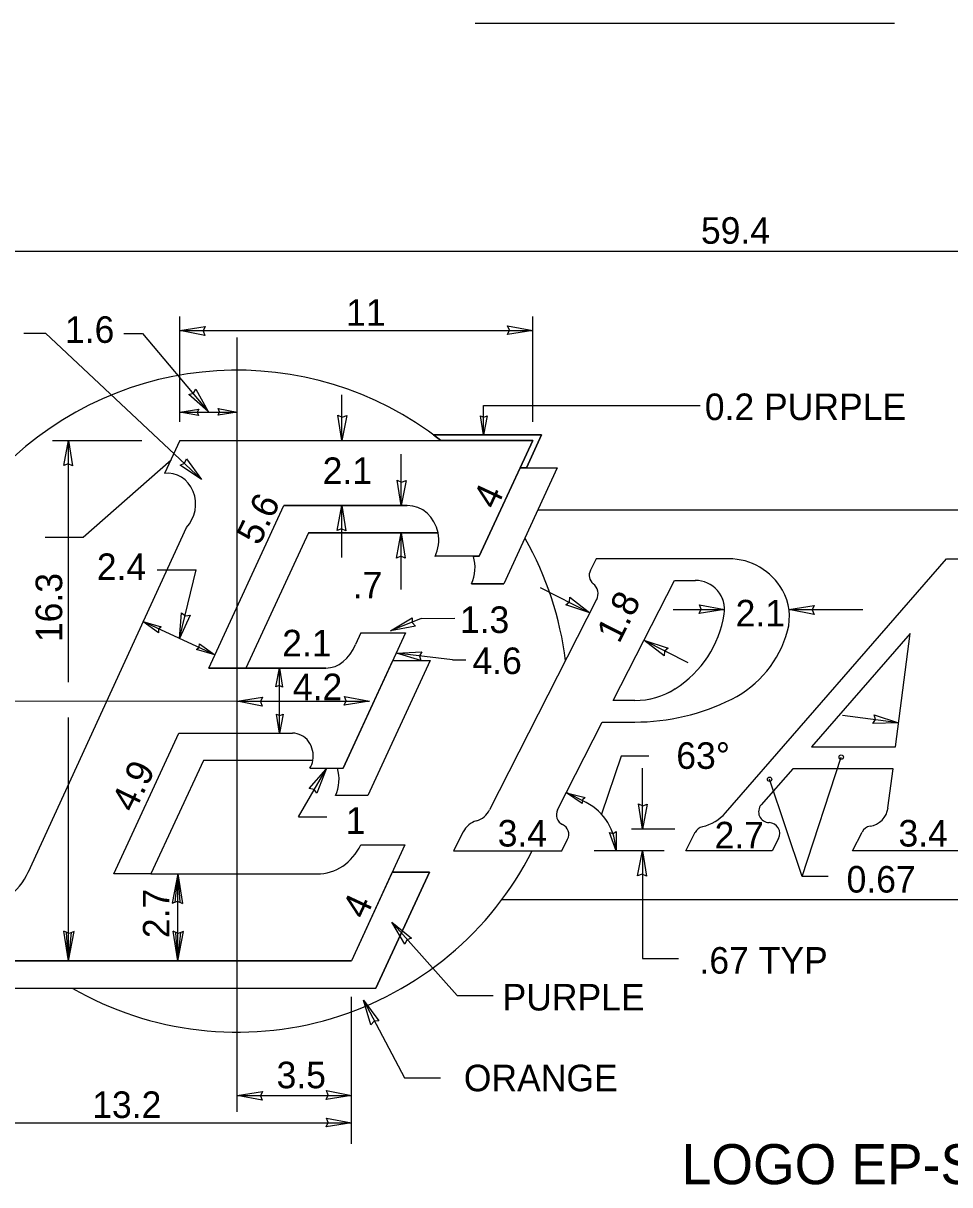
# Model space of a CAD drawing. Extents: x 10268197 to 10268826, y 2141503 to 2142677.
# Drawn here: x 10268506.08 to 10268526.03, y 2142338.69 to 2142363.7 of the extents above; entities that cross this region are included whole.
import ezdxf

# ---------------------------------------------------------------- set-up
doc = ezdxf.new("R2010")
doc.units = 0
doc.layers.add('Default', color=7, linetype='Continuous')
doc.layers.add('TextDetails', color=7, linetype='Continuous')

msp = doc.modelspace()

# ---------------------------------------------------------------- linework, layer by layer
at = {"layer": 'Default'}
for p, q in [((10268501.67, 2142358.79), (10268542.432, 2142358.79)), ((10268509.455, 2142355.114), (10268509.455, 2142357.385)), ((10268517.054, 2142355.114), (10268517.054, 2142357.385)), ((10268509.455, 2142357.079), (10268517.054, 2142357.079)), ((10268508.25, 2142357.02), (10268508.653, 2142357.02)), ((10268508.653, 2142357.02), (10268510.066, 2142355.339)), ((10268510.689, 2142349.102), (10268510.689, 2142356.928)), ((10268512.945, 2142354.713), (10268512.945, 2142355.696)), ((10268509.455, 2142355.326), (10268510.689, 2142355.326)), ((10268515.994, 2142354.837), (10268515.994, 2142355.47)), ((10268515.994, 2142355.47), (10268520.663, 2142355.47)), ((10268515.079, 2142354.713), (10268514.916, 2142354.837)), ((10268514.916, 2142354.837), (10268517.247, 2142354.837)), ((10268514.916, 2142354.837), (10268517.247, 2142354.837)), ((10268517.247, 2142354.837), (10268516.918, 2142354.124)), ((10268517.247, 2142354.837), (10268516.918, 2142354.124)), ((10268506.717, 2142354.713), (10268508.635, 2142354.713)), ((10268507.062, 2142349.514), (10268507.062, 2142354.713)), ((10268509.455, 2142354.713), (10268509.127, 2142354)), ((10268509.455, 2142354.713), (10268517.054, 2142354.713)), ((10268517.054, 2142354.713), (10268515.079, 2142354.713)), ((10268517.054, 2142354.713), (10268515.902, 2142352.22)), ((10268516.783, 2142354.124), (10268517.054, 2142354.713)), ((10268507.376, 2142352.632), (10268509.266, 2142354.295)), ((10268514.223, 2142353.314), (10268514.223, 2142354.42)), ((10268515.902, 2142352.22), (10268516.783, 2142354.124)), ((10268517.582, 2142354.124), (10268516.429, 2142351.63)), ((10268517.582, 2142354.124), (10268516.429, 2142351.63)), ((10268516.783, 2142354.124), (10268517.582, 2142354.124)), ((10268516.783, 2142354.124), (10268517.582, 2142354.124)), ((10268516.783, 2142354.124), (10268517.582, 2142354.124)), ((10268516.918, 2142354.124), (10268516.783, 2142354.124)), ((10268510.081, 2142349.813), (10268511.696, 2142353.314)), ((10268510.081, 2142349.813), (10268511.696, 2142353.314)), ((10268510.081, 2142349.813), (10268511.696, 2142353.314)), ((10268511.696, 2142353.314), (10268514.353, 2142353.314)), ((10268511.696, 2142353.314), (10268514.353, 2142353.314)), ((10268512.196, 2142353.314), (10268511.696, 2142353.314)), ((10268511.696, 2142353.314), (10268514.353, 2142353.314)), ((10268511.696, 2142353.314), (10268514.353, 2142353.314)), ((10268514.353, 2142353.314), (10268512.196, 2142353.314)), ((10268512.945, 2142352.193), (10268512.945, 2142353.314)), ((10268542.432, 2142353.216), (10268517.161, 2142353.216)), ((10268506.2, 2142345.432), (10268509.597, 2142352.844)), ((10268506.56, 2142352.632), (10268507.376, 2142352.632)), ((10268512.225, 2142352.724), (10268510.879, 2142349.813)), ((10268512.225, 2142352.724), (10268510.879, 2142349.813)), ((10268512.225, 2142352.724), (10268510.879, 2142349.813)), ((10268515.015, 2142352.724), (10268512.225, 2142352.724)), ((10268512.225, 2142352.724), (10268515.015, 2142352.724)), ((10268515.015, 2142352.724), (10268512.225, 2142352.724)), ((10268515.015, 2142352.724), (10268512.723, 2142352.724)), ((10268514.223, 2142351.509), (10268514.223, 2142352.724)), ((10268515.902, 2142352.22), (10268514.952, 2142352.22)), ((10268515.775, 2142352.22), (10268515.902, 2142352.22)), ((10268518.424, 2142352.168), (10268518.296, 2142351.919)), ((10268521.277, 2142352.168), (10268518.424, 2142352.168)), ((10268521.206, 2142346.697), (10268525.961, 2142352.168)), ((10268525.961, 2142352.168), (10268526.799, 2142352.168)), ((10268508.966, 2142351.929), (10268509.811, 2142351.929)), ((10268509.448, 2142350.452), (10268509.811, 2142351.929)), ((10268515.734, 2142351.63), (10268516.429, 2142351.63)), ((10268516.429, 2142351.63), (10268515.734, 2142351.63)), ((10268517.213, 2142351.552), (10268518.287, 2142351.004)), ((10268518.789, 2142349.118), (10268520.107, 2142351.703)), ((10268518.789, 2142349.118), (10268520.107, 2142351.702)), ((10268520.107, 2142351.703), (10268520.556, 2142351.703)), ((10268520.107, 2142351.702), (10268520.556, 2142351.702)), ((10268518.431, 2142351.288), (10268516.126, 2142346.762)), ((10268520.08, 2142351.074), (10268521.185, 2142351.074)), ((10268522.572, 2142351.074), (10268524.16, 2142351.074)), ((10268510.213, 2142350.099), (10268508.659, 2142350.815)), ((10268514.653, 2142350.882), (10268513.989, 2142350.617)), ((10268514.653, 2142350.882), (10268515.379, 2142350.886)), ((10268514.318, 2142350.57), (10268512.973, 2142347.658)), ((10268513.354, 2142350.57), (10268513.24, 2142350.322)), ((10268513.354, 2142350.57), (10268514.318, 2142350.57)), ((10268525.182, 2142350.562), (10268523.055, 2142348.116)), ((10268525.182, 2142350.561), (10268523.055, 2142348.116)), ((10268524.863, 2142348.116), (10268525.182, 2142350.562)), ((10268524.863, 2142348.116), (10268525.182, 2142350.561)), ((10268519.45, 2142350.413), (10268520.391, 2142349.934)), ((10268515.328, 2142349.989), (10268514.118, 2142350.138)), ((10268510.081, 2142349.813), (10268512.603, 2142349.813)), ((10268512.603, 2142349.813), (10268510.081, 2142349.813)), ((10268510.879, 2142349.813), (10268510.081, 2142349.813)), ((10268510.081, 2142349.813), (10268512.603, 2142349.813)), ((10268512.603, 2142349.813), (10268510.081, 2142349.813)), ((10268510.58, 2142349.813), (10268511.38, 2142349.813)), ((10268511.601, 2142348.414), (10268511.601, 2142349.813)), ((10268512.973, 2142347.658), (10268514.045, 2142349.98)), ((10268514.844, 2142349.98), (10268513.501, 2142347.07)), ((10268514.844, 2142349.98), (10268513.501, 2142347.07)), ((10268514.045, 2142349.98), (10268514.844, 2142349.98)), ((10268514.045, 2142349.98), (10268514.844, 2142349.98)), ((10268515.328, 2142349.989), (10268515.616, 2142349.99)), ((10268510.689, 2142349.102), (10268503.564, 2142349.091)), ((10268510.689, 2142340.264), (10268510.689, 2142349.102)), ((10268510.689, 2142349.102), (10268513.54, 2142349.102)), ((10268519.251, 2142349.118), (10268518.789, 2142349.118)), ((10268519.251, 2142349.118), (10268518.789, 2142349.118)), ((10268524.931, 2142348.637), (10268523.728, 2142348.793)), ((10268507.062, 2142343.516), (10268507.062, 2142348.748)), ((10268517.589, 2142346.762), (10268518.552, 2142348.652)), ((10268518.552, 2142348.652), (10268519.251, 2142348.652)), ((10268508.033, 2142345.382), (10268509.434, 2142348.414)), ((10268508.033, 2142345.382), (10268509.434, 2142348.414)), ((10268509.434, 2142348.414), (10268511.884, 2142348.414)), ((10268509.434, 2142348.414), (10268511.884, 2142348.414)), ((10268523.055, 2142348.116), (10268524.863, 2142348.116)), ((10268523.055, 2142348.116), (10268524.863, 2142348.116)), ((10268509.963, 2142347.824), (10268508.832, 2142345.382)), ((10268509.963, 2142347.824), (10268508.832, 2142345.382)), ((10268512.319, 2142347.824), (10268509.963, 2142347.824)), ((10268512.319, 2142347.824), (10268509.963, 2142347.824)), ((10268518.956, 2142347.917), (10268518.533, 2142346.672)), ((10268519.554, 2142347.917), (10268518.956, 2142347.917)), ((10268522.857, 2142345.331), (10268523.697, 2142347.897)), ((10268512.012, 2142346.61), (10268512.604, 2142347.635)), ((10268512.258, 2142347.658), (10268512.973, 2142347.658)), ((10268512.848, 2142347.658), (10268512.973, 2142347.658)), ((10268519.416, 2142346.346), (10268519.416, 2142347.658)), ((10268522.652, 2142347.649), (10268521.976, 2142346.873)), ((10268524.814, 2142347.649), (10268522.652, 2142347.649)), ((10268524.704, 2142346.809), (10268524.814, 2142347.649)), ((10268522.857, 2142345.331), (10268522.153, 2142347.421)), ((10268513.501, 2142347.07), (10268512.806, 2142347.07)), ((10268513.501, 2142347.07), (10268512.806, 2142347.07)), ((10268518.207, 2142346.918), (10268517.78, 2142347.137)), ((10268512.012, 2142346.61), (10268512.62, 2142346.61)), ((10268515.559, 2142346.291), (10268515.351, 2142345.88)), ((10268520.116, 2142346.346), (10268519.183, 2142346.346)), ((10268520.348, 2142345.88), (10268520.55, 2142346.279)), ((10268523.942, 2142345.88), (10268524.148, 2142346.284)), ((10268517.679, 2142345.88), (10268517.805, 2142346.129)), ((10268522.349, 2142346.149), (10268522.211, 2142345.88)), ((10268514.304, 2142346.011), (10268513.151, 2142343.516)), ((10268513.354, 2142346.011), (10268514.304, 2142346.011)), ((10268515.351, 2142345.88), (10268517.679, 2142345.88)), ((10268519.883, 2142345.881), (10268518.378, 2142345.881)), ((10268519.416, 2142345.881), (10268519.416, 2142343.565)), ((10268522.211, 2142345.88), (10268520.348, 2142345.88)), ((10268526.27, 2142345.88), (10268523.942, 2142345.88)), ((10268508.832, 2142345.382), (10268508.033, 2142345.382)), ((10268508.832, 2142345.382), (10268508.033, 2142345.382)), ((10268508.832, 2142345.382), (10268512.415, 2142345.382)), ((10268509.414, 2142345.382), (10268509.291, 2142344.753)), ((10268509.414, 2142345.382), (10268509.35, 2142344.778)), ((10268509.414, 2142343.516), (10268509.414, 2142345.382)), ((10268509.414, 2142345.382), (10268509.514, 2142344.749)), ((10268509.414, 2142345.382), (10268509.456, 2142344.776)), ((10268514.03, 2142345.421), (10268513.151, 2142343.516)), ((10268514.83, 2142345.421), (10268513.678, 2142342.926)), ((10268513.678, 2142342.926), (10268514.83, 2142345.421)), ((10268514.03, 2142345.421), (10268514.83, 2142345.421)), ((10268514.83, 2142345.421), (10268514.03, 2142345.421)), ((10268523.415, 2142345.331), (10268522.857, 2142345.331)), ((10268509.291, 2142344.753), (10268509.404, 2142344.8)), ((10268509.404, 2142344.8), (10268509.514, 2142344.749)), ((10268516.394, 2142344.832), (10268538.161, 2142344.832)), ((10268514.018, 2142344.346), (10268515.427, 2142342.766)), ((10268507.062, 2142343.516), (10268506.961, 2142344.148)), ((10268507.071, 2142344.098), (10268506.961, 2142344.148)), ((10268507.062, 2142343.516), (10268507.019, 2142344.121)), ((10268507.062, 2142343.516), (10268507.183, 2142344.144)), ((10268507.062, 2142343.516), (10268507.125, 2142344.12)), ((10268507.183, 2142344.144), (10268507.071, 2142344.098)), ((10268509.414, 2142343.516), (10268509.314, 2142344.148)), ((10268509.423, 2142344.098), (10268509.314, 2142344.148)), ((10268509.414, 2142343.516), (10268509.371, 2142344.121)), ((10268509.414, 2142343.516), (10268509.536, 2142344.144)), ((10268509.414, 2142343.516), (10268509.477, 2142344.12)), ((10268509.536, 2142344.144), (10268509.423, 2142344.098)), ((10268519.416, 2142343.565), (10268520.192, 2142343.565)), ((10268504.099, 2142343.516), (10268513.151, 2142343.516)), ((10268513.151, 2142343.516), (10268505.489, 2142343.516)), ((10268505.217, 2142342.926), (10268513.678, 2142342.926)), ((10268505.217, 2142342.926), (10268513.678, 2142342.926)), ((10268513.151, 2142339.572), (10268513.151, 2142342.741)), ((10268513.409, 2142342.664), (10268514.296, 2142340.997)), ((10268515.427, 2142342.766), (10268516.202, 2142342.766)), ((10268514.296, 2142340.997), (10268515.071, 2142340.997)), ((10268510.689, 2142340.615), (10268513.151, 2142340.615)), ((10268504.124, 2142340.023), (10268513.151, 2142340.023))]:
    msp.add_line(p, q, dxfattribs=at)
for points in [[(10268509.455, 2142357.079), (10268509.999, 2142357.165), (10268509.958, 2142357.072), (10268509.995, 2142356.975)], [(10268517.054, 2142357.079), (10268516.51, 2142356.994), (10268516.551, 2142357.087), (10268516.514, 2142357.183)], [(10268510.066, 2142355.339), (10268509.65, 2142355.7), (10268509.748, 2142355.729), (10268509.798, 2142355.82)], [(10268509.455, 2142355.326), (10268509.863, 2142355.39), (10268509.832, 2142355.32), (10268509.86, 2142355.248)], [(10268510.689, 2142355.326), (10268510.281, 2142355.262), (10268510.312, 2142355.331), (10268510.284, 2142355.404)], [(10268512.945, 2142354.713), (10268512.86, 2142355.257), (10268512.953, 2142355.216), (10268513.05, 2142355.253)], [(10268515.994, 2142354.837), (10268515.93, 2142355.245), (10268516, 2142355.214), (10268516.072, 2142355.243)], [(10268514.916, 2142354.837), (10268515.079, 2142354.713), (10268517.054, 2142354.713), (10268516.783, 2142354.124), (10268516.918, 2142354.124), (10268517.247, 2142354.837)], [(10268507.062, 2142354.713), (10268507.147, 2142354.169), (10268507.054, 2142354.21), (10268506.957, 2142354.173)], [(10268509.92, 2142353.873), (10268509.465, 2142354.183), (10268509.559, 2142354.223), (10268509.597, 2142354.319)], [(10268514.223, 2142353.314), (10268514.138, 2142353.858), (10268514.231, 2142353.817), (10268514.328, 2142353.854)], [(10268512.945, 2142353.314), (10268513.031, 2142352.77), (10268512.938, 2142352.811), (10268512.841, 2142352.774)], [(10268514.223, 2142352.724), (10268514.309, 2142352.18), (10268514.216, 2142352.221), (10268514.119, 2142352.184)], [(10268518.287, 2142351.004), (10268517.764, 2142351.175), (10268517.843, 2142351.24), (10268517.853, 2142351.343)], [(10268521.185, 2142351.074), (10268520.641, 2142350.988), (10268520.682, 2142351.082), (10268520.644, 2142351.178)], [(10268522.572, 2142351.074), (10268523.116, 2142351.16), (10268523.075, 2142351.067), (10268523.112, 2142350.97)], [(10268508.659, 2142350.815), (10268509.057, 2142350.703), (10268508.999, 2142350.652), (10268508.995, 2142350.575)], [(10268509.448, 2142350.452), (10268509.495, 2142351.001), (10268509.576, 2142350.939), (10268509.679, 2142350.952)], [(10268513.989, 2142350.617), (10268514.462, 2142350.898), (10268514.458, 2142350.796), (10268514.529, 2142350.72)], [(10268510.213, 2142350.099), (10268509.815, 2142350.212), (10268509.873, 2142350.262), (10268509.878, 2142350.34)], [(10268519.45, 2142350.413), (10268519.973, 2142350.242), (10268519.895, 2142350.178), (10268519.884, 2142350.075)], [(10268514.118, 2142350.138), (10268514.668, 2142350.165), (10268514.617, 2142350.076), (10268514.644, 2142349.976)], [(10268511.601, 2142349.813), (10268511.665, 2142349.405), (10268511.595, 2142349.436), (10268511.523, 2142349.408)], [(10268510.689, 2142349.102), (10268511.233, 2142349.187), (10268511.192, 2142349.094), (10268511.229, 2142348.997)], [(10268513.54, 2142349.102), (10268512.996, 2142349.016), (10268513.037, 2142349.109), (10268513, 2142349.206)], [(10268511.601, 2142348.414), (10268511.537, 2142348.822), (10268511.606, 2142348.791), (10268511.679, 2142348.819)], [(10268524.931, 2142348.637), (10268524.381, 2142348.622), (10268524.433, 2142348.709), (10268524.408, 2142348.81)], [(10268512.604, 2142347.635), (10268512.407, 2142347.121), (10268512.346, 2142347.204), (10268512.244, 2142347.22)], [(10268517.781, 2142347.131), (10268518.182, 2142347.028), (10268518.125, 2142346.976), (10268518.122, 2142346.898)], [(10268519.416, 2142346.346), (10268519.331, 2142346.89), (10268519.424, 2142346.849), (10268519.521, 2142346.886)], [(10268518.848, 2142345.884), (10268518.711, 2142346.273), (10268518.784, 2142346.256), (10268518.851, 2142346.296)], [(10268519.416, 2142345.881), (10268519.502, 2142345.337), (10268519.409, 2142345.378), (10268519.312, 2142345.34)], [(10268514.018, 2142344.346), (10268514.444, 2142343.997), (10268514.347, 2142343.966), (10268514.299, 2142343.874)], [(10268513.409, 2142342.664), (10268513.74, 2142342.224), (10268513.638, 2142342.217), (10268513.57, 2142342.138)], [(10268510.689, 2142340.615), (10268511.233, 2142340.701), (10268511.192, 2142340.608), (10268511.229, 2142340.511)], [(10268513.151, 2142340.615), (10268512.607, 2142340.529), (10268512.648, 2142340.623), (10268512.611, 2142340.719)], [(10268513.151, 2142340.023), (10268512.607, 2142339.937), (10268512.648, 2142340.03), (10268512.611, 2142340.127)]]:
    msp.add_lwpolyline(points, close=True, dxfattribs=at)
msp.add_lwpolyline([(10268506.098, 2142357.023), (10268506.565, 2142357.023), (10268509.92, 2142353.873)], dxfattribs=at)
for centre in [(10268523.696, 2142347.897), (10268522.153, 2142347.42)]:
    msp.add_circle(centre, 0.0466, dxfattribs=at)
for centre, radius, start, end in [((10268510.689, 2142349.102), 7.125, 51.9618, 218.2529), ((10268510.689, 2142349.102), 7.125, 7.0123, 29.4243), ((10268521.276, 2142350.84), 1.327, 29.4315, 90), ((10268518.504, 2142351.813), 0.233, 152.9784, 231.1602), ((10268518.183, 2142351.414), 0.279, 333.0027, 51.1602), ((10268520.555, 2142351.073), 0.629, 351.076, 90), ((10268520.555, 2142351.074), 0.629, 351.076, 90), ((10268521.418, 2142350.92), 1.164, 344.7074, 29.4315), ((10268518.876, 2142351.337), 2.329, 302.4206, 351.076), ((10268518.876, 2142351.337), 2.329, 302.4206, 351.076), ((10268520.295, 2142351.227), 2.329, 296.6431, 344.7074), ((10268519.25, 2142350.747), 1.63, 270, 302.4206), ((10268519.251, 2142350.748), 1.63, 270, 302.4206), ((10268519.25, 2142353.309), 4.657, 270, 296.6431), ((10268517.679, 2142345.881), 1.164, 0, 62.9941), ((10268522.151, 2142346.721), 0.233, 138.9824, 268.6869), ((10268524.243, 2142346.868), 0.466, 279.2397, 352.5632), ((10268515.711, 2142346.973), 0.466, 286.4317, 332.9959), ((10268517.796, 2142346.656), 0.233, 152.9884, 244.7832), ((10268520.502, 2142347.309), 0.931, 282.7162, 318.9966), ((10268515.974, 2142346.079), 0.466, 106.4317, 152.9742), ((10268517.598, 2142346.235), 0.233, 333.0239, 64.7832), ((10268520.758, 2142346.173), 0.233, 102.7162, 153.0239), ((10268522.141, 2142346.255), 0.233, 332.9784, 88.6869), ((10268524.355, 2142346.179), 0.233, 99.2397, 153.0239), ((10268510.689, 2142349.102), 7.125, 240.0889, 333.1198)]:
    msp.add_arc(centre, radius, start, end, dxfattribs=at)
for centre, major_axis, ratio, start_param, end_param in [((10268509.205, 2142353.342), (0, 0.665), 0.889671, 3.865417, 6.41824), ((10268514.353, 2142352.567), (0, 0.747), 0.906667, 4.924065, 6.283185), ((10268514.353, 2142352.567), (0, 0.747), 0.906667, 4.924772, 6.283185), ((10268514.353, 2142352.567), (0, 0.747), 0.906667, 4.924772, 6.283185), ((10268514.353, 2142352.567), (0, 0.747), 0.906667, 4.924772, 6.283185), ((10268514.353, 2142352.567), (0, 0.747), 0.906667, 4.228038, 4.924065), ((10268515.135, 2142351.978), (0, 0.747), 0.906667, 4.227342, 5.041732), ((10268515.135, 2142351.978), (0, 0.747), 0.906667, 4.227342, 5.041732), ((10268512.603, 2142350.748), (0, 0.933), 0.764971, 3.141593, 4.241405), ((10268511.883, 2142347.923), (0, 0.491), 0.906667, 4.510784, 6.283185), ((10268511.883, 2142347.923), (0, 0.491), 0.906667, 4.510784, 6.283185), ((10268511.883, 2142347.923), (0, 0.491), 0.906667, 4.144801, 4.510784), ((10268512.207, 2142347.418), (0, 0.747), 0.906667, 4.227342, 5.041732), ((10268512.207, 2142347.418), (0, 0.747), 0.906667, 4.227342, 5.041732), ((10268512.414, 2142346.548), (0, 1.166), 0.906667, 3.141593, 4.233038), ((10268505.116, 2142346.048), (0, 1.356), 0.897229, 3.121696, 4.241135)]:
    msp.add_ellipse(centre, major_axis=major_axis, ratio=ratio, start_param=start_param, end_param=end_param, dxfattribs=at)
at = {"layer": 'TextDetails'}
msp.add_line((10268515.816, 2142363.696), (10268524.842, 2142363.696), dxfattribs=at)

# ---------------------------------------------------------------- texts
at = {"layer": 'Default'}
for s, height, p in [('59.4', 0.5717, (10268520.677, 2142358.949)), ('11', 0.5717, (10268513.036, 2142357.182)), ('1.6', 0.5717, (10268506.983, 2142356.815)), ('0.2 PURPLE', 0.5717, (10268520.76, 2142355.153)), ('2.1', 0.5717, (10268512.531, 2142353.777)), ('2.4', 0.5717, (10268507.669, 2142351.71)), ('.7', 0.5717, (10268513.178, 2142351.313)), ('2.1', 0.5717, (10268521.424, 2142350.711)), ('1.3', 0.5717, (10268515.486, 2142350.57)), ('2.1', 0.5717, (10268511.66, 2142350.066)), ('4.6', 0.5717, (10268515.757, 2142349.686)), ('4.2', 0.5717, (10268511.89, 2142349.123)), ('63°', 0.5717, (10268520.146, 2142347.645)), ('1', 0.572, (10268513.029, 2142346.244)), ('3.4', 0.5717, (10268516.301, 2142345.973)), ('3.4', 0.5717, (10268524.93, 2142345.973)), ('2.7', 0.5717, (10268520.97, 2142345.933)), ('0.67', 0.5717, (10268523.813, 2142344.982)), ('.67 TYP', 0.5717, (10268520.645, 2142343.237)), ('PURPLE', 0.5717, (10268516.405, 2142342.444)), ('3.5', 0.5717, (10268511.539, 2142340.77)), ('ORANGE', 0.5717, (10268515.571, 2142340.705)), ('13.2', 0.5717, (10268507.57, 2142340.13))]:
    msp.add_text(s, height=height, dxfattribs=at).set_placement(p)
for s, height, rotation, p in [('5.6', 0.5717, 64.0244, (10268511.164, 2142352.431)), ('4', 0.572, 65.0602, (10268516.266, 2142353.206)), ('16.3', 0.5717, 90, (10268506.923, 2142350.373)), ('1.8', 0.5717, 62.9907, (10268518.913, 2142350.323)), ('4.9', 0.5717, 64.0244, (10268508.472, 2142346.679)), ('2.7', 0.5717, 90, (10268509.233, 2142344.001)), ('4', 0.572, 65.0602, (10268513.448, 2142344.381))]:
    msp.add_text(s, height=height, rotation=rotation, dxfattribs=at).set_placement(p)
at = {"layer": 'TextDetails'}
msp.add_text('LOGO EP-SPECIAL', height=0.8624, dxfattribs=at).set_placement((10268520.259, 2142338.704))

doc.saveas('drawing.dxf')
